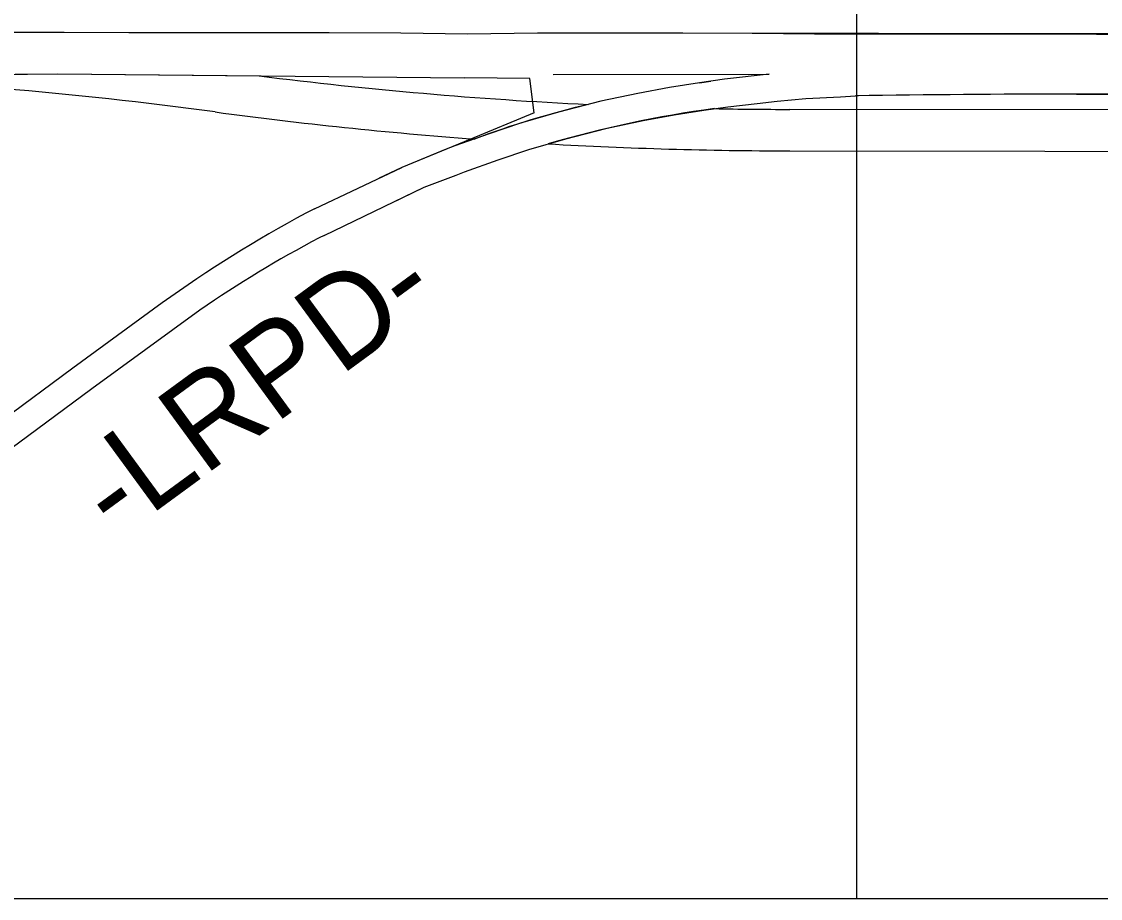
# Model space of a CAD drawing. Extents: x 2241278 to 2254132, y 649924 to 670434.
# Drawn here: x 2248087 to 2248712, y 662535 to 663043 of the extents above; entities that cross this region are included whole.
import ezdxf

# ---------------------------------------------------------------- set-up
doc = ezdxf.new("R2010")
doc.units = 0
for name, color, linetype in [('Pattern 4', 7, 'Continuous'), ('Prop DSN Text', 7, 'Continuous'), ('Prop EOT', 7, 'Continuous'), ('Prop RDY Alternate Text Yellow', 7, 'Continuous'), ('Prop Shade Heavy', 7, 'Continuous')]:
    doc.layers.add(name, color=color, linetype=linetype)

msp = doc.modelspace()

# ---------------------------------------------------------------- linework, layer by layer
at = {"layer": 'Pattern 4'}
for p, q in [((2248256.9186574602, 662934.5455357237), (2248252.014731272, 662931.9389525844)), ((2248262.5025082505, 662919.1278512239), (2248259.678465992, 662917.6801460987))]:
    msp.add_line(p, q, dxfattribs=at)
for points in [[(2248748.5551320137, 663035.2078753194), (2248709.569692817, 663035.4523364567), (2248669.6461878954, 663035.5464317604), (2248628.2619666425, 663035.5182476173), (2248587.9962907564, 663035.632422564), (2248546.371543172, 663035.662418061), (2248510.311641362, 663036.0516162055), (2248470.2386517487, 663036.059114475), (2248425.2354624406, 663036.0532913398), (2248386.101186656, 663036.0530466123), (2248345.643766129, 663035.5713561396), (2248306.986998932, 663036.1613770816), (2248265.567576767, 663036.2722761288), (2248229.5543715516, 663036.3244754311), (2248189.9512624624, 663036.3103149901), (2248149.629663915, 663036.3298486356), (2248112.101711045, 663036.4882494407), (2248065.4694329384, 663036.5665502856)], [(2247885.1541067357, 663010.867667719), (2248108.3612273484, 663012.5461497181), (2248343.7468128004, 663010.3186732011)], [(2248697.996508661, 663000.8356622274), (2248701.6137060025, 663000.8835208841), (2248747.9133080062, 663000.8673465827), (2248781.9784494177, 663000.6100270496), (2248810.475118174, 663001.1631734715), (2248837.7173311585, 663001.1015211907), (2248859.9624694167, 663002.3098727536), (2248881.2325595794, 663003.0213568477), (2248898.018917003, 663004.038114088), (2248925.4469335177, 663005.4166768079), (2248959.443907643, 663007.2343067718), (2248984.239088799, 663008.4419906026), (2249001.7018443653, 663009.432305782), (2249018.1251939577, 663010.3309372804), (2249031.9899260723, 663010.9687554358), (2249051.592922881, 663012.1635181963), (2249068.0811014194, 663012.7258490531), (2249088.0510972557, 663012.798439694), (2249104.8641020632, 663012.8310636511), (2249128.325150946, 663012.8929500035), (2249139.3899553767, 663012.772964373)], [(2248384.1761782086, 662990.0163908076), (2248381.5728692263, 663009.9141437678), (2248343.7468128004, 663010.3186732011)], [(2248384.1761782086, 662990.0163908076), (2248346.8267302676, 662974.6649145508), (2248307.5958074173, 662958.3791652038)], [(2248256.9186574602, 662934.5455357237), (2248307.5958074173, 662958.3791652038)], [(2248262.5025082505, 662919.1278512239), (2248320.496441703, 662946.9406935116)], [(2248190.711917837, 662875.8806967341), (2248128.1782898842, 662830.341816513), (2248085.5821708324, 662798.8993242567), (2248041.2737742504, 662766.5786950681), (2247996.138771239, 662733.4675637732), (2247949.133786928, 662698.8348647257), (2247907.231608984, 662667.8760655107), (2247881.174003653, 662648.5143410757), (2247830.650295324, 662611.8232152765), (2247810.3265469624, 662596.7410412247)], [(2248168.754366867, 662880.0633044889), (2248117.066324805, 662842.1984165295), (2248075.994747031, 662811.8773064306), (2248031.152912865, 662779.2544673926), (2247987.354140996, 662747.154369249), (2247938.577262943, 662711.5606965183), (2247898.4844190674, 662682.8156246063), (2247870.759370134, 662662.3242279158)]]:
    msp.add_lwpolyline(points, dxfattribs=at)
for centre, major_axis, ratio, start_param, end_param in [((2248615.066728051, 662255.5876527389), (-594.3042269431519, -488.64991366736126), 0.9976114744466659, 4.517336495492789, 4.644928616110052), ((2248579.7174341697, 662312.153549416), (-676.3871199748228, -108.97215876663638), 0.9996591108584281, 5.038759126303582, 5.156543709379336)]:
    msp.add_ellipse(centre, major_axis=major_axis, ratio=ratio, start_param=start_param, end_param=end_param, dxfattribs=at)
at = {"layer": 'Prop DSN Text'}
for p, q in [((2248570.7292612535, 663585.4551830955), (2248570.7574885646, 662535.4424933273)), ((2248395.225136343, 663012.2057993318), (2248520.2254132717, 663012.429869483)), ((2247330.516632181, 662535.4449286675), (2251198.4499030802, 662535.4373335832))]:
    msp.add_line(p, q, dxfattribs=at)
for points in [[(2249147.7259531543, 663035.3138990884), (2248395.2535438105, 663036.2060279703)], [(2248520.2254132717, 663012.429869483), (2248494.256647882, 663009.4340136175), (2248479.9215735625, 663007.4338435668), (2248462.508989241, 663004.6946279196), (2248444.069039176, 663001.2760685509), (2248422.7575522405, 662996.754036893), (2248398.3064615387, 662990.51881723), (2248376.268538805, 662984.1448510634), (2248358.051250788, 662977.9435787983), (2248338.2766244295, 662970.8810330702), (2248333.2081967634, 662969.0115164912)], [(2248338.9494457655, 662954.005963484), (2248343.828616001, 662955.8740958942), (2248363.3202732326, 662962.8355786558), (2248381.0718350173, 662968.878314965), (2248402.5070441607, 662975.0779599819), (2248426.3963820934, 662981.1699282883), (2248447.18834987, 662985.5817244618), (2248465.210964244, 662988.9229144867), (2248482.270490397, 662991.6065897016), (2248496.2792922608, 662993.5612350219), (2248513.189914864, 662995.5121089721), (2248524.807079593, 662996.8290775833), (2248541.4705025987, 662998.2678919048), (2248561.505341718, 662999.3446872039), (2248570.2105680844, 662999.8789508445)], [(2248333.2081967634, 662969.0115164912), (2248307.5958074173, 662958.3791652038), (2248294.347054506, 662952.1476983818)], [(2248300.9813680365, 662937.5816169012), (2248320.496441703, 662946.9406935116), (2248338.9494457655, 662954.005963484)]]:
    msp.add_lwpolyline(points, dxfattribs=at)
msp.add_arc((2248689.937627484, 655542.7146767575), 7458.125339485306, 88.99914965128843, 90.91982228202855, dxfattribs=at)
at = {"layer": 'Prop EOT'}
msp.add_lwpolyline([(2248479.9215735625, 663007.4338435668), (2248486.4066720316, 663008.3387080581)], dxfattribs=at)
msp.add_arc((2248689.937627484, 655542.7146767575), 7458.125339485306, 90.90631604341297, 90.91982228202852, dxfattribs=at)
at = {"layer": 'Prop Shade Heavy'}
msp.add_line((2247952.379067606, 663011.3731887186), (2248108.3612273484, 663012.5461497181), dxfattribs=at)
for points in [[(2248108.3612273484, 663012.5461497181), (2248224.9072071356, 663011.4432638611)], [(2249131.461170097, 662991.3331516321), (2248532.0654020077, 662992.0437933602)], [(2248532.03699483, 662968.0438101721), (2249122.589470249, 662967.3436530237)]]:
    msp.add_lwpolyline(points, dxfattribs=at)
for centre, radius, start, end in [((2247867.2806268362, 660524.8289491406), 2488, 82.32545349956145, 88.03989843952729), ((2248535.010279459, 665480.0420737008), 2487.999999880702, 262.8400622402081, 267.24757363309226), ((2248541.5554916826, 662460.4053479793), 549.1618887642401, 103.26628399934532, 110.46740864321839), ((2248535.010279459, 665480.0420737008), 2511.999999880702, 262.3254534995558, 265.76550274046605), ((2248575.7207187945, 662342.5983097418), 655.7043857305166, 97.64346270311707, 106.25115154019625), ((2248535.010279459, 665480.0420737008), 2487.999999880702, 268.92901187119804, 269.93218284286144), ((2248535.010279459, 665480.0420737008), 2511.999999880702, 266.7414319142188, 269.9321828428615)]:
    msp.add_arc(centre, radius, start, end, dxfattribs=at)

# ---------------------------------------------------------------- texts
at = {"layer": 'Prop RDY Alternate Text Yellow'}
msp.add_text('-LRPD-', height=52.59375, rotation=36.21349404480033, dxfattribs=at).set_placement((2248142.4811661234, 662742.6664708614))

doc.saveas('drawing.dxf')
